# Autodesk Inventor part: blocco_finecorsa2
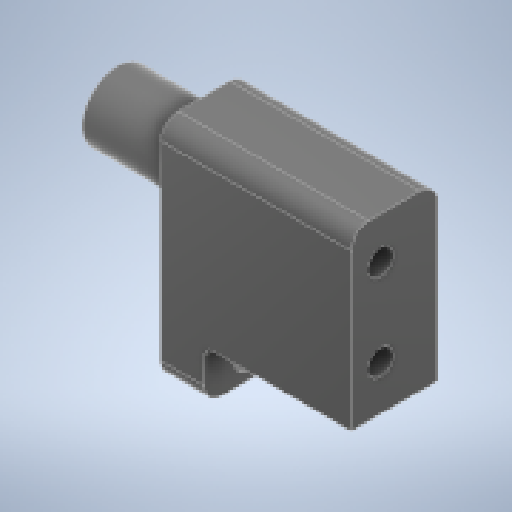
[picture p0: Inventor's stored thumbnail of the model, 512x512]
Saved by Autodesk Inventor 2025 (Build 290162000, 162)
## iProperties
Created: 2026-03
Part Number: blocco_finecorsa2
Material: Generico
Document SubType Name: Modeling
Designer: Ryzen5700u
Density: 1 g/cm^3
Appearance: Liscia - Nero
Author: Ryzen5700u
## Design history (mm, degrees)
sketch "Schizzo1"
  geometry: L1 (10, 5)-(-10, 5); L2 (-10, 5)-(-10, -5); L3 (-10, -5)-(10, -5); L4 (10, -5)-(10, 5); L5 (10, 5)-(-10, -5); L6 (-10, 5)-(10, -5); 1 further point
  constraints: 12 end point, 2 midpoint, 2 parallel, 1 horizontal, 1 perpendicular
  dimensions: "d0" = 20 distance of L3.end L2.end; "d1" = 10 distance of L2.end L1.end
extrude "Estrusione1" new body sketch "Schizzo1" distance "d2" = 22; taper "d3" = 0 deg
sketch "Schizzo2"
  geometry: C1 r 4 at (0, 4); 1 further point
  constraints: 1 centre point
  dimensions: "d4" = 8 diameter of C1; "d5" = 4 distance of point (0, 0) C1.centre
extrude "Estrusione2" join sketch "Schizzo2" distance "d6" = 10; taper "d7" = 0 deg
sketch "Schizzo3"
  geometry: C1 r 1.25 at (-1.6, 5.125) reference; C2 r 1.25 at (-1.6, -4.875) reference; 1 further point
hole "Foro1" sketch "Schizzo3" at (-1.6, 5.125), (-1.6, -4.875) diameter "d9" = 2.9; stored, may be unused: countersink angle "d13" = 90 deg, drill point angle "d15" = 118 deg; dims "d10" = 6, "d11" = 5.5, "d12" = 2.9, "d14" = 8
sketch "Schizzo4"
  geometry: L1 (5, -10)-(-5, -10) reference; L2 (5, 10)-(5, -10) reference; L3 (-5, 10)-(5, 10) reference; L4 (-5, -10)-(-5, 10) reference; L5 (5, -10)-(-5, -10) reference; L6 (5, -10)-(-5, -10); L7 (-5, -10)-(-5, -16); L8 (-5, -16)-(5, -16); L9 (5, -16)-(5, -10); C1 r 4 at (0, 4) reference; 2 further points
  constraints: 8 end point, 2 parallel, 1 horizontal, 1 perpendicular
  dimensions: "d16" = 6 distance of L7.end L6.end
extrude "Estrusione3" join sketch "Schizzo4" distance "d17" = 5; taper "d18" = 0 deg
fillet "Raccordo2" dims "d19" = 1
sketch "Schizzo5"
  geometry: L1 (-5, -16)-(5, -16) reference; 2 further points
  dimensions: "d27" = 2.5 distance from line of L1 point (0, -13.5)
hole "Foro2" sketch "Schizzo5" at (0, -13.5) diameter "d20" = 2.9; stored, may be unused: countersink angle "d24" = 90 deg, drill point angle "d26" = 118 deg; dims "d21" = 6, "d22" = 4, "d23" = 2, "d25" = 8
fillet "Raccordo3" dims "d28" = 2
node "Solido1"
node "Riferimento1"
node "Riferimento2"
node "Linea chiusa proiettata1"
